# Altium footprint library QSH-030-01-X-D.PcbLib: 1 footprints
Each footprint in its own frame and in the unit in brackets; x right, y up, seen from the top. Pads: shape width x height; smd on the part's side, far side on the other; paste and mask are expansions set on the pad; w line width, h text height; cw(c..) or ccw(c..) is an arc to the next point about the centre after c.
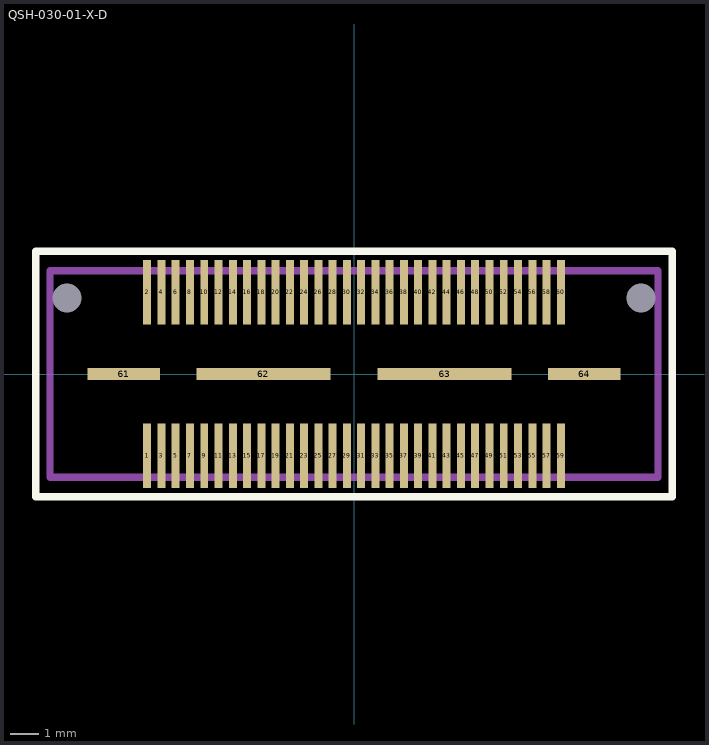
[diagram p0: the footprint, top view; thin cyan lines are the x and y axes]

## QSH-030-01-X-D [mm]
pads (66):
  rect 0.28x2.27 smd mask+0.05: 1(-7.25,-2.865) 2(-7.25,2.865) 3(-6.75,-2.865) 4(-6.75,2.865) 5(-6.25,-2.865) 6(-6.25,2.865) 7(-5.75,-2.865) 8(-5.75,2.865) 9(-5.25,-2.865) 10(-5.25,2.865) 11(-4.75,-2.865) 12(-4.75,2.865) 13(-4.25,-2.865) 14(-4.25,2.865) 15(-3.75,-2.865) 16(-3.75,2.865) 17(-3.25,-2.865) 18(-3.25,2.865) 19(-2.75,-2.865) 20(-2.75,2.865) 21(-2.25,-2.865) 22(-2.25,2.865) 23(-1.75,-2.865) 24(-1.75,2.865) 25(-1.25,-2.865) 26(-1.25,2.865) 27(-0.75,-2.865) 28(-0.75,2.865) 29(-0.25,-2.865) 30(-0.25,2.865) 31(0.25,-2.865) 32(0.25,2.865) 33(0.75,-2.865) 34(0.75,2.865) 35(1.25,-2.865) 36(1.25,2.865) 37(1.75,-2.865) 38(1.75,2.865) 39(2.25,-2.865) 40(2.25,2.865) 41(2.75,-2.865) 42(2.75,2.865) 43(3.25,-2.865) 44(3.25,2.865) 45(3.75,-2.865) 46(3.75,2.865) 47(4.25,-2.865) 48(4.25,2.865) 49(4.75,-2.865) 50(4.75,2.865) 51(5.25,-2.865) 52(5.25,2.865) 53(5.75,-2.865) 54(5.75,2.865) 55(6.25,-2.865) 56(6.25,2.865) 57(6.75,-2.865) 58(6.75,2.865) 59(7.25,-2.865) 60(7.25,2.865)
  rect 2.54x0.43 smd mask+0.05: 61(-8.065,0) 64(8.065,0)
  rect 4.7x0.43 smd mask+0.05: 62(-3.175,0) 63(3.175,0)
  round 0 hole 1.02 unplated: 65(-10.065,2.67) 66(10.065,2.67)
Top Overlay:
  lines w0.254: -11.155,-4.3 -11.155,4.3 11.155,4.3 11.155,-4.3 -11.155,-4.3
Mechanical 1:
  lines w0.254: -10.655,-3.62 -10.655,3.62 10.655,3.62 10.655,-3.62 -10.655,-3.62
  text "J1" at -0.446,-0.457 h0.76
